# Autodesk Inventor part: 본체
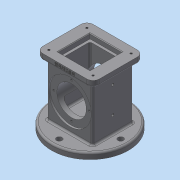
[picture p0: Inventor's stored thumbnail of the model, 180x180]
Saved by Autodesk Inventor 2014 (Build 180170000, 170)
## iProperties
Created: 2018-10
Part Number: 본체
Material: 일반
Document SubType Name: Modeling
Designer: 602-19
Density: 1 g/cm^3
Appearance: 기본값
Author: 602-19
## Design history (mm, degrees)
sketch "스케치1"
  geometry: L1 (-37, 33)-(37, 33); L2 (37, 33)-(37, -33); L3 (37, -33)-(-37, -33); L4 (-37, -33)-(-37, 33); L5 (-37, 33)-(37, -33); L6 (37, 33)-(-37, -33); 1 further point
  constraints: 12 end point, 2 midpoint, 2 parallel, 1 horizontal, 1 perpendicular
  dimensions: "d0" = 66 distance of L1.end L2.end; "d1" = 74 distance of L1.start L1.end
extrude "돌출1" new body sketch "스케치1" distance "d2" = 108; taper "d3" = 0 deg
sketch "스케치2"
  geometry: C1 r 62.5 at (0, 0); 1 further point
  constraints: 1 centre point, 1 coincident
  dimensions: "d4" = 125 diameter of C1
extrude "돌출2" join sketch "스케치2" distance "d5" = 10; taper "d6" = 0 deg
sketch "스케치3"
  geometry: L1 (-46, 41)-(46, 41); L2 (46, 41)-(46, -41); L3 (46, -41)-(-46, -41); L4 (-46, -41)-(-46, 41); L5 (-46, 41)-(46, -41); L6 (46, 41)-(-46, -41); 1 further point
  constraints: 12 end point, 2 midpoint, 2 parallel, 1 horizontal, 1 perpendicular
  dimensions: "d7" = 82 distance of L1.end L2.end; "d8" = 92 distance of L1.start L1.end
extrude "돌출3" join sketch "스케치3" distance "d9" = 10; taper "d10" = 0 deg
fillet "모깎기1" dims "d11" = 10
fillet "모깎기2" dims "d12" = 3
fillet "모깎기3" dims "d13" = 3
sketch "스케치4"
  geometry: L1 (-26, 26)-(26, 26); L2 (26, 26)-(26, -26); L3 (26, -26)-(-26, -26); L4 (-26, -26)-(-26, 26); L5 (-26, 26)-(26, -26); L6 (26, 26)-(-26, -26); 1 further point
  constraints: 12 end point, 2 midpoint, 2 parallel, 1 horizontal, 1 perpendicular
  dimensions: "d14" = 52 distance of L1.start L1.end; "d15" = 52 distance of L1.end L2.end
extrude "돌출4" cut sketch "스케치4" distance "d16" = 8; taper "d17" = 0 deg
sketch "스케치5"
  geometry: L1 (-22, 22)-(22, 22); L2 (22, 22)-(22, -22); L3 (22, -22)-(-22, -22); L4 (-22, -22)-(-22, 22); L5 (-22, 22)-(22, -22); L6 (22, 22)-(-22, -22); 1 further point
  constraints: 12 end point, 2 midpoint, 2 parallel, 1 horizontal, 1 perpendicular
  dimensions: "d18" = 44 distance of L2.end L3.end; "d19" = 44 distance of L1.end L2.end
extrude "돌출5" cut sketch "스케치5" distance "d20" = 74; taper "d21" = 0 deg
chamfer "모따기1" distance "d22" = 1; stored, may be unused: second distance "d23" = 2, angle "d24" = 45 deg
fillet "모깎기4" dims "d25" = 3
sketch "스케치6"
  geometry: L1 (34, -95)-(34, 56.625); L2 (-26.109, -41)-(126.764, -41); C1 r 35 at (34, -41)
  constraints: 4 end point, 2 point on line, 1 centre point, 1 perpendicular, 1 vertical
  dimensions: "d26" = 54 distance from line of L1.start L2; "d27" = 70 diameter of C1
extrude "돌출6" cut sketch "스케치6" distance "d28" = 3; taper "d29" = 0 deg
sketch "스케치7"
  geometry: C1 r 35 at (0, 0) reference; C2 r 24 at (0, 0); 1 further point
  constraints: 1 centre point, 1 coincident
  dimensions: "d30" = 48 diameter of C2
extrude "돌출7" cut sketch "스케치7" stored distance "d31" = 3; taper "d32" = 0 deg
sketch "스케치8"
  geometry: C1 r 35 at (34, 41); A1 r 24 centre (34, 41) between (53, 55.663) and (15, 55.663) reference; 1 further point
  constraints: 1 centre point, 1 coincident
  dimensions: "d33" = 70 diameter of C1
extrude "돌출8" cut sketch "스케치8" distance "d34" = 3; taper "d35" = 0 deg
sketch "스케치9"
  geometry: C1 r 28 at (0, 0); 1 further point
  constraints: 1 centre point, 1 coincident
  dimensions: "d36" = 56 diameter of C1
extrude "돌출9" cut sketch "스케치9" distance "d37" = 18; taper "d38" = -10 deg
sketch "스케치11" dims "d39" = 100
  geometry: L1 (0, 0)-(0, 85.068); 2 further points
  constraints: 2 end point, 1 coincident, 1 point on line, 1 vertical, 1 vertical alignment, 2 other
hole "구멍1" sketch "스케치11" at (0, 50) diameter "d40" = 9; stored, may be unused: countersink angle "d44" = 90 deg, drill point angle "d46" = 118 deg; dims "d41" = 6, "d42" = 4, "d43" = 2, "d45" = 8
hole "구멍2" diameter "d52" = 3.242; stored, may be unused: countersink angle "d56" = 90 deg, drill point angle "d58" = 118 deg; dims "d50" = 10, "d51" = 10, "d53" = 4, "d54" = 4, "d55" = 2, "d57" = 6
sketch "스케치12"
  geometry: C1 r 24 at (0, 0) reference; C2 r 35 at (0, 0) reference; 2 further points
  dimensions: "d65" = 29 distance of C1.centre point (0, 29)
hole "구멍3" sketch "스케치12" at (0, 29) diameter "d66" = 3.242; stored, may be unused: countersink angle "d70" = 90 deg, drill point angle "d72" = 118 deg; dims "d67" = 4, "d68" = 4, "d69" = 2, "d71" = 6
sketch "스케치13"
  geometry: L1 (95, 30)-(-44.757, 30); 1 further point
  constraints: 2 end point, 1 horizontal, 1 point on line
  dimensions: "d76" = 37 distance of L1.start point (58, 30)
hole "구멍4" sketch "스케치13" at (58, 30) diameter "d77" = 4.134; stored, may be unused: countersink angle "d81" = 90 deg, drill point angle "d83" = 118 deg; dims "d78" = 20, "d79" = 4, "d80" = 2, "d82" = 26
sketch "스케치14"
  geometry: L1 (36, -108)-(36, 23.076); L2 (9.831, -4)-(64.046, -4); L3 (72, 0)-(0, 0) reference; L4 (19.461, -1.519)-(52.644, -1.519); L5 (52.644, -1.519)-(52.644, -6.323); L6 (52.644, -6.323)-(19.461, -6.323); L7 (19.461, -6.323)-(19.461, -1.519)
  constraints: 4 end point, 1 perpendicular, 1 vertical, 2 other
  dimensions: "d87" = 4 distance between parallel lines of L2 L3
feature "엠보싱1" sketch "스케치14" dims "d0" = 66, "d1" = 74, "d88" = 0.5, "d89" = 0
fillet "모깎기5" dims "d90" = 3
node "솔리드1"
pattern_circular "원형 패턴1" dims angle "d48" = 360 deg
pattern_linear "직사각형 패턴1" dims "d61" = 72, "d64" = 62
pattern_circular "원형 패턴2" dims angle "d74" = 360 deg
mirror "대칭1"
pattern_linear "직사각형 패턴2" dims "d86" = 43
node "투영된 루프1"
node "투영된 루프3"
